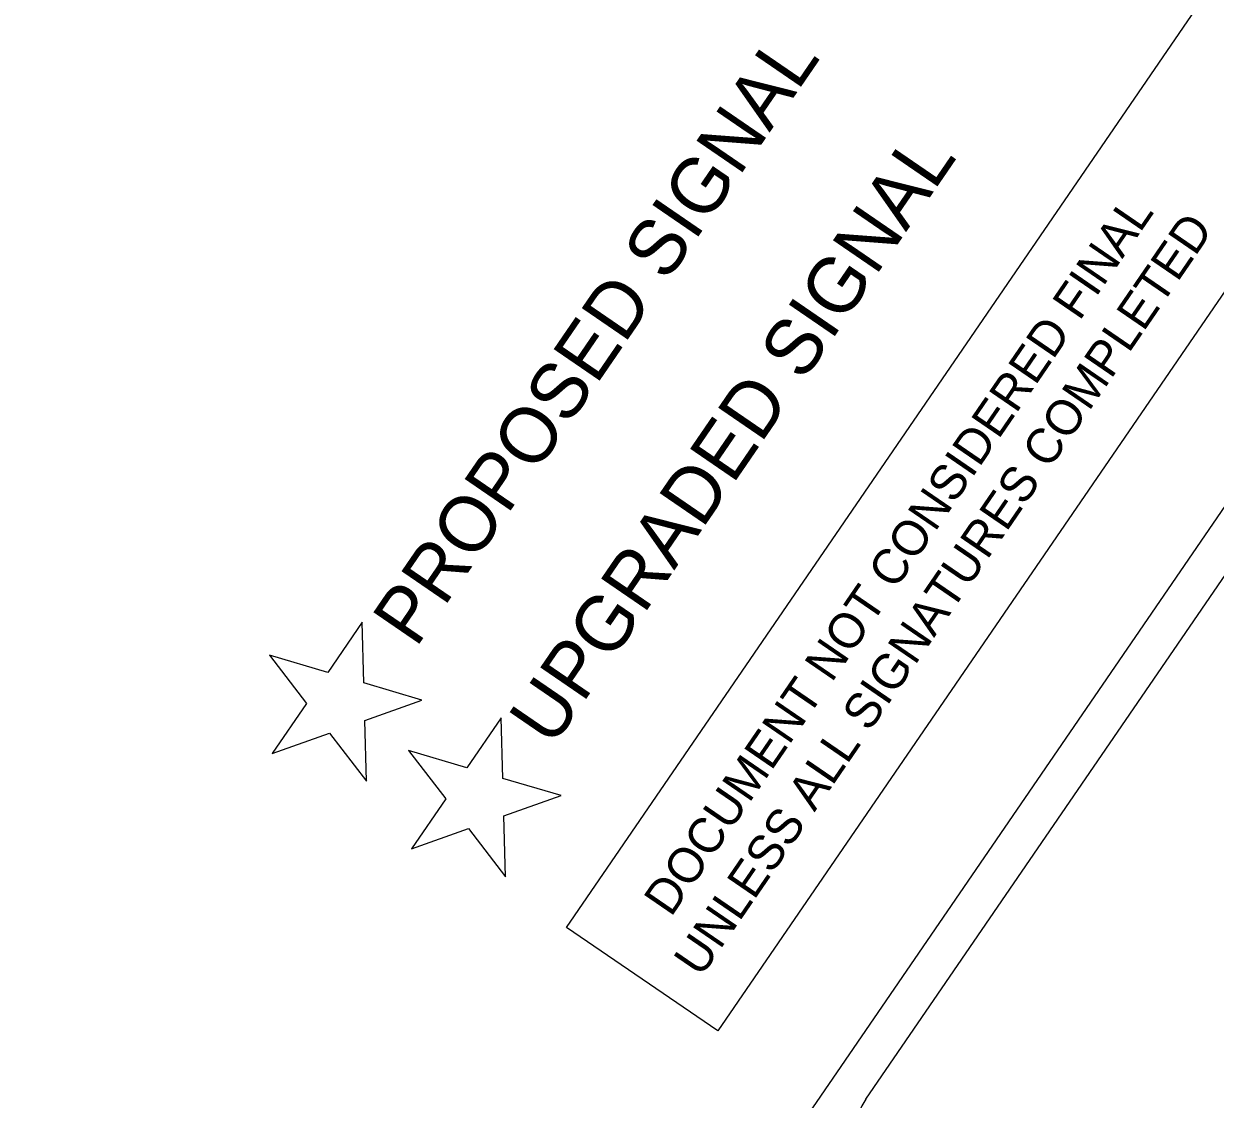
# Model space of a CAD drawing. Extents: x 2312641 to 2338852, y 590461 to 618614.
# Drawn here: x 2333435 to 2335572, y 609408 to 611337 of the extents above; entities that cross this region are included whole.
import ezdxf

# ---------------------------------------------------------------- set-up
doc = ezdxf.new("R2010")
doc.units = 0
for name, color, linetype in [('Exist Property Iron Pin Cogo Number', 7, 'Continuous'), ('Exist Roads EOP Other Text', 7, 'Continuous'), ('Exist Structure Minor Storm Sewer Manhole Cogo Elevation', 7, 'Continuous'), ('Exist Utilities Power Pole CELL', 7, 'Continuous')]:
    doc.layers.add(name, color=color, linetype=linetype)

msp = doc.modelspace()

# ---------------------------------------------------------------- linework, layer by layer
at = {"layer": 'Exist Property Iron Pin Cogo Number'}
for p, q in [((2324877.7, 594842), (2336116.1, 611240.6)), ((2334945.3, 609408.4), (2336173.8, 611201))]:
    msp.add_line(p, q, dxfattribs=at)
msp.add_arc((2335060.8, 609329.2), 140, 145.5761, 235.5761, dxfattribs=at)
at = {"layer": 'Exist Roads EOP Other Text'}
for p, q in [((2334408.3, 609716.6), (2335571.7, 611414.2)), ((2335843.1, 611228.3), (2334679.7, 609530.7)), ((2334679.7, 609530.7), (2334408.3, 609716.6))]:
    msp.add_line(p, q, dxfattribs=at)
at = {"layer": 'Exist Structure Minor Storm Sewer Manhole Cogo Elevation'}
for points in [[(2333941.6, 610118.3), (2333880.1, 610028.5), (2333982.6, 610065), (2334049.1, 609978.6), (2334046.1, 610087.6), (2334148.7, 610124.1), (2334044.2, 610154.9), (2334041.2, 610263.8), (2333979.7, 610173.9), (2333875.1, 610204.7), (2333941.6, 610118.3)], [(2333941.6, 610118.3), (2333880.1, 610028.5), (2333982.6, 610065), (2334049.1, 609978.6), (2334046.1, 610087.6), (2334148.7, 610124.1), (2334044.2, 610154.9), (2334041.2, 610263.8), (2333979.7, 610173.9), (2333875.1, 610204.7), (2333941.6, 610118.3)], [(2334191.4, 609947.1), (2334129.9, 609857.3), (2334232.4, 609893.8), (2334298.9, 609807.4), (2334295.9, 609916.4), (2334398.5, 609952.9), (2334294, 609983.7), (2334291, 610092.6), (2334229.5, 610002.7), (2334124.9, 610033.5), (2334191.4, 609947.1)]]:
    msp.add_lwpolyline(points, dxfattribs=at)

# ---------------------------------------------------------------- texts
at = {"layer": 'Exist Roads EOP Other Text'}
for s, p in [('DOCUMENT NOT CONSIDERED FINAL', (2334595.4, 609733.4)), ('UNLESS ALL SIGNATURES COMPLETED', (2334649.1, 609625.1))]:
    msp.add_text(s, height=63, rotation=55.5761, dxfattribs=at).set_placement(p)
at = {"layer": 'Exist Utilities Power Pole CELL'}
for s, p in [('PROPOSED SIGNAL', (2334137.9, 610216.2)), ('UPGRADED SIGNAL', (2334382.7, 610037.6))]:
    msp.add_text(s, height=100, rotation=55.5761, dxfattribs=at).set_placement(p)

doc.saveas('drawing.dxf')
